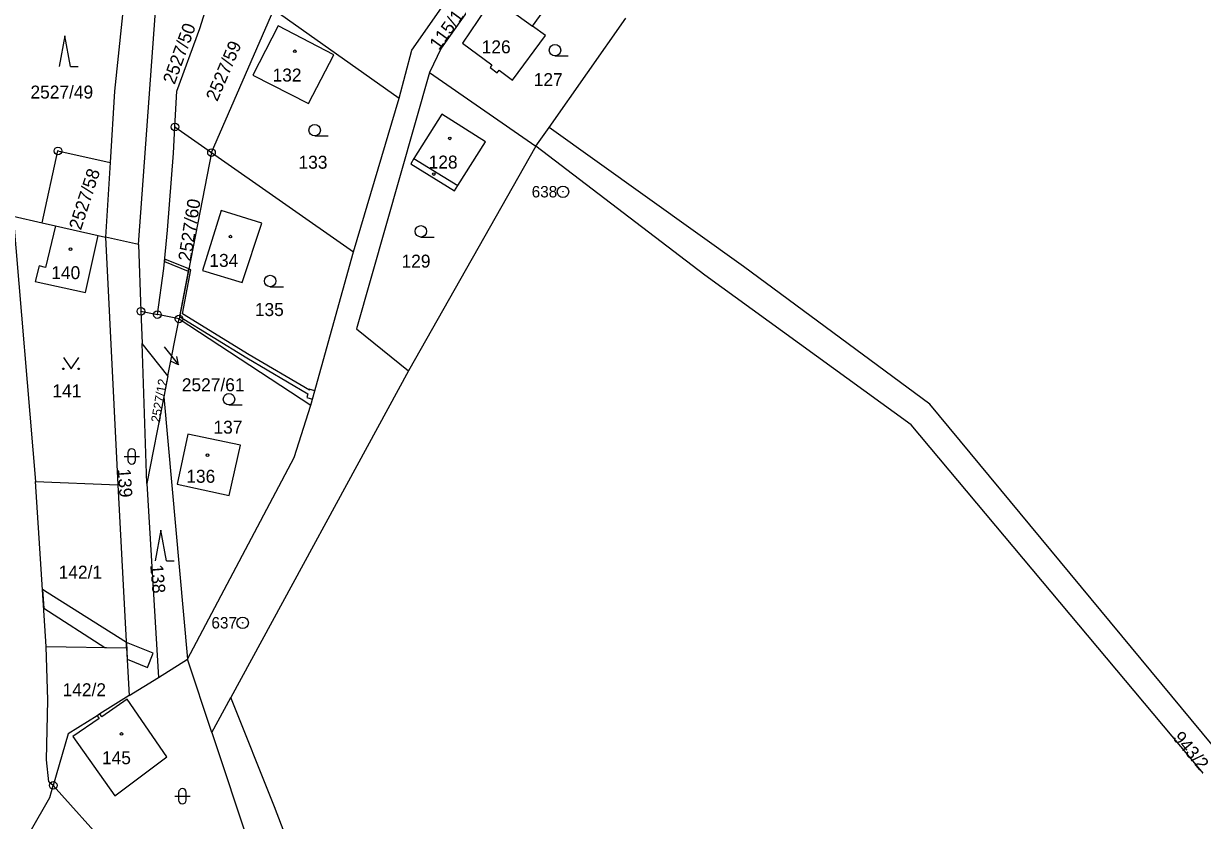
# Model space of a CAD drawing. Extents: x -562167 to -556918, y -1077891 to -1070763.
# Drawn here: x -558717.1 to -558563.6, y -1073031.5 to -1072927 of the extents above; entities that cross this region are included whole.
import ezdxf

# ---------------------------------------------------------------- set-up
doc = ezdxf.new("R2010")
doc.units = 0
for name, color, linetype in [('Hranice parcel', 7, 'Continuous'), ('Parcelní čísla', 7, 'Continuous'), ('Pop  PČ popisy', 7, 'Continuous'), ('Vnitřní kresba', 7, 'Continuous'), ('Věcná břemena k části', 7, 'Continuous'), ('Značky bodu BP', 7, 'Continuous'), ('Značky budov', 7, 'Continuous'), ('Značky kultur', 7, 'Continuous')]:
    doc.layers.add(name, color=color, linetype=linetype)

msp = doc.modelspace()

# ---------------------------------------------------------------- linework, layer by layer
at = {"layer": 'Hranice parcel'}
for p, q in [((-558701.98, -1072956.02), (-558699.1, -1072916.31)), ((-558692.42, -1072943.94), (-558684.24, -1072925.17)), ((-558684.24, -1072925.17), (-558667.85, -1072936.79)), ((-558648.2, -1072940.64), (-558638.13, -1072926.33)), ((-558663.85, -1072933.45), (-558649.94, -1072943.11)), ((-558673.83, -1072956.97), (-558667.85, -1072936.79)), ((-558697.22, -1072940.58), (-558692.42, -1072943.94)), ((-558649.94, -1072943.11), (-558648.2, -1072940.64)), ((-558692.42, -1072943.94), (-558696.67, -1072965.75)), ((-558692.42, -1072943.94), (-558673.83, -1072956.97)), ((-558649.94, -1072943.11), (-558666.61, -1072972.57)), ((-558705.7, -1072945.25), (-558706.29, -1072955.05)), ((-558718.41, -1072952.27), (-558715.49, -1072987.07)), ((-558718.41, -1072952.27), (-558714.62, -1072953.15)), ((-558714.62, -1072953.15), (-558712.86, -1072953.56)), ((-558712.86, -1072953.56), (-558707.25, -1072954.83)), ((-558707.25, -1072954.83), (-558706.29, -1072955.05)), ((-558706.29, -1072955.05), (-558704.68, -1072987.52)), ((-558701.98, -1072956.02), (-558706.29, -1072955.05)), ((-558701.98, -1072956.02), (-558701.67, -1072964.76)), ((-558679.39, -1072977.06), (-558673.83, -1072956.97)), ((-558701.67, -1072964.76), (-558699.51, -1072965.19)), ((-558701.67, -1072964.76), (-558701.52, -1072968.96)), ((-558696.67, -1072965.75), (-558699.51, -1072965.19)), ((-558698.12, -1072973.21), (-558696.67, -1072965.75)), ((-558696.67, -1072965.75), (-558679.39, -1072977.06)), ((-558700.87, -1072987.32), (-558701.52, -1072968.96)), ((-558698.12, -1072973.21), (-558701.52, -1072968.96)), ((-558698.12, -1072973.21), (-558698.66, -1072975.99)), ((-558666.61, -1072972.57), (-558689.88, -1073015.41)), ((-558698.66, -1072975.99), (-558700.87, -1072987.32)), ((-558698.66, -1072975.99), (-558695.57, -1073010.37)), ((-558715.49, -1072987.07), (-558704.68, -1072987.52)), ((-558714.07, -1073008.73), (-558715.49, -1072987.07)), ((-558700.87, -1072987.32), (-558699.38, -1073012.76)), ((-558704.68, -1072987.52), (-558703.54, -1073008.89)), ((-558713.87, -1073015.76), (-558714.07, -1073008.73)), ((-558714.07, -1073008.73), (-558703.54, -1073008.89)), ((-558703.54, -1073008.89), (-558703.2, -1073015.15)), ((-558699.38, -1073012.76), (-558695.57, -1073010.37)), ((-558692.37, -1073019.99), (-558695.57, -1073010.37)), ((-558703.2, -1073015.15), (-558699.38, -1073012.76)), ((-558703.2, -1073015.15), (-558707.03, -1073017.56)), ((-558692.37, -1073019.99), (-558689.88, -1073015.41)), ((-558707.03, -1073017.56), (-558707.39, -1073017.78)), ((-558707.39, -1073017.78), (-558707.14, -1073018.16)), ((-558706.78, -1073017.92), (-558707.03, -1073017.56)), ((-558692.37, -1073019.99), (-558687.05, -1073036.02)), ((-558713.15, -1073026.92), (-558713.74, -1073026.44)), ((-558713.15, -1073026.92), (-558698.1, -1073043.74))]:
    msp.add_line(p, q, dxfattribs=at)
for points in [[(-558702.73, -1072912.92), (-558705.13, -1072935.89), (-558705.7, -1072945.25)], [(-558652.4, -1072916.22), (-558662.34, -1072930.27), (-558663.85, -1072933.45)], [(-558667.85, -1072936.79), (-558666.17, -1072930.51), (-558658.29, -1072919.24)], [(-558648.32, -1072924.55), (-558653.29, -1072920.66), (-558655.5, -1072923.6), (-558659.52, -1072929.61), (-558655.67, -1072932.46), (-558655.92, -1072932.8), (-558655, -1072933.48), (-558654.75, -1072933.14), (-558652.99, -1072934.45), (-558648.65, -1072928.6), (-558650.36, -1072927.35), (-558648.32, -1072924.55)], [(-558697.22, -1072940.58), (-558696.96, -1072935.88), (-558693.96, -1072927.69), (-558692.53, -1072923.19)], [(-558676.41, -1072931.12), (-558683.67, -1072927.34), (-558686.99, -1072933.79), (-558679.71, -1072937.53), (-558676.41, -1072931.12)], [(-558663.85, -1072933.45), (-558673.43, -1072967.05), (-558666.61, -1072972.57)], [(-558662.26, -1072938.92), (-558665.9, -1072944.73), (-558666.32, -1072945.41), (-558660.57, -1072948.95), (-558660.14, -1072948.28), (-558656.54, -1072942.55), (-558662.26, -1072938.92)], [(-558699.51, -1072965.19), (-558698.65, -1072959.15), (-558698.2, -1072954.14), (-558697.41, -1072944.04), (-558697.22, -1072940.58)], [(-558496.99, -1073103.87), (-558502.94, -1073096.71), (-558515.86, -1073079.61), (-558541.04, -1073045.13), (-558560.05, -1073023.14), (-558598.3, -1072976.95), (-558622.72, -1072958.89), (-558648.2, -1072940.64)], [(-558714.62, -1072953.15), (-558712.53, -1072943.72), (-558705.7, -1072945.25)], [(-558501.24, -1073106.42), (-558504.83, -1073102.06), (-558527.47, -1073069.53), (-558543.69, -1073047.48), (-558560.44, -1073027.77), (-558600.75, -1072979.63), (-558627.78, -1072960.02), (-558649.94, -1072943.11)], [(-558691.16, -1072951.54), (-558693.58, -1072959.4), (-558688.39, -1072961), (-558685.83, -1072953.2), (-558691.16, -1072951.54)], [(-558712.86, -1072953.56), (-558714.17, -1072959), (-558715.01, -1072958.8), (-558715.51, -1072960.86), (-558708.94, -1072962.31), (-558707.25, -1072954.83)], [(-558695.57, -1073010.37), (-558681.57, -1072983.94), (-558679.39, -1072977.06)], [(-558690.09, -1072988.89), (-558688.63, -1072982.31), (-558695.51, -1072980.88), (-558696.91, -1072987.44), (-558690.09, -1072988.89)], [(-558713.74, -1073026.44), (-558714.05, -1073023.57), (-558713.87, -1073015.76)], [(-558707.14, -1073018.16), (-558710.58, -1073020.53), (-558705.1, -1073028.3), (-558698.27, -1073023.19), (-558703.45, -1073015.63), (-558706.78, -1073017.92)], [(-558666.41, -1073067.91), (-558673.57, -1073057.52), (-558684.16, -1073029.73), (-558689.88, -1073015.41)], [(-558707.39, -1073017.78), (-558711.21, -1073020.18), (-558713.15, -1073026.92)], [(-558716.16, -1073033.01), (-558713.62, -1073028.53), (-558713.15, -1073026.92)]]:
    msp.add_lwpolyline(points, dxfattribs=at)
at = {"layer": 'Pop  PČ popisy'}
for p, q in [((-558698.61, -1072969.43), (-558696.76, -1072971.79)), ((-558696.76, -1072971.79), (-558697.77, -1072971.31)), ((-558696.76, -1072971.79), (-558696.98, -1072970.7))]:
    msp.add_line(p, q, dxfattribs=at)
at = {"layer": 'Vnitřní kresba'}
for p, q in [((-558655.5, -1072923.6), (-558650.36, -1072927.35)), ((-558665.9, -1072944.73), (-558660.14, -1072948.28))]:
    msp.add_line(p, q, dxfattribs=at)
at = {"layer": 'Věcná břemena k části'}
for points in [[(-558695.46, -1072959.51), (-558695.4, -1072959.21), (-558698.54, -1072957.94), (-558698.57, -1072958.23)], [(-558695.4, -1072959.21), (-558695.46, -1072959.51), (-558696.61, -1072965.46), (-558687.79, -1072970.88), (-558679.78, -1072975.56), (-558679.91, -1072976.08), (-558679.17, -1072976.28), (-558678.88, -1072975.2), (-558679.61, -1072974.97), (-558679.6, -1072975.09), (-558687.5, -1072970.47), (-558696.24, -1072965.1), (-558695.11, -1072959.33)], [(-558714.56, -1073001.24), (-558714.4, -1073003.68), (-558706.38, -1073008.85), (-558703.54, -1073008.89), (-558703.57, -1073008.18), (-558713.93, -1073001.61)], [(-558703.46, -1073010.39), (-558700.82, -1073011.46), (-558700.07, -1073009.6), (-558703.57, -1073008.18)]]:
    msp.add_lwpolyline(points, close=True, dxfattribs=at)
at = {"layer": 'Značky bodu BP'}
for centre, radius in [((-558697.22, -1072940.58), 0.5), ((-558697.22, -1072940.58), 0.0303), ((-558712.53, -1072943.72), 0.5), ((-558712.53, -1072943.72), 0.0303), ((-558692.42, -1072943.94), 0.5), ((-558692.42, -1072943.94), 0.0303), ((-558646.37, -1072949.08), 0.75), ((-558646.37, -1072949.08), 0.03), ((-558701.67, -1072964.76), 0.5), ((-558701.67, -1072964.76), 0.0303), ((-558699.51, -1072965.19), 0.5), ((-558699.51, -1072965.19), 0.0303), ((-558696.67, -1072965.75), 0.5), ((-558696.67, -1072965.75), 0.0303), ((-558688.33, -1073005.6), 0.75), ((-558688.33, -1073005.6), 0.03), ((-558713.15, -1073026.92), 0.5), ((-558713.15, -1073026.92), 0.0303)]:
    msp.add_circle(centre, radius, dxfattribs=at)
at = {"layer": 'Značky budov'}
for centre in [(-558681.51, -1072930.67), (-558661.21, -1072942.08), (-558663.3, -1072946.76), (-558689.95, -1072954.97), (-558710.89, -1072956.6), (-558692.94, -1072983.61), (-558704.22, -1073020.18)]:
    msp.add_circle(centre, 0.175, dxfattribs=at)
at = {"layer": 'Značky kultur'}
for p, q in [((-558711.64, -1072928.64), (-558712.39, -1072932.64)), ((-558710.89, -1072932.64), (-558711.64, -1072928.64)), ((-558647.42, -1072931.27), (-558645.67, -1072931.27)), ((-558710.89, -1072932.64), (-558709.89, -1072932.64)), ((-558678.9, -1072941.76), (-558677.15, -1072941.76)), ((-558664.98, -1072955.02), (-558663.23, -1072955.02)), ((-558684.74, -1072961.54), (-558682.99, -1072961.54)), ((-558690.13, -1072977.04), (-558688.38, -1072977.04)), ((-558703.87, -1072983.78), (-558701.87, -1072983.78)), ((-558703.37, -1072983.28), (-558703.37, -1072984.28)), ((-558702.37, -1072984.28), (-558702.37, -1072983.28)), ((-558699.06, -1072993.47), (-558699.81, -1072997.47)), ((-558698.31, -1072997.47), (-558699.06, -1072993.47)), ((-558698.31, -1072997.47), (-558697.31, -1072997.47)), ((-558697.23, -1073028.34), (-558695.23, -1073028.34)), ((-558696.73, -1073027.84), (-558696.73, -1073028.84)), ((-558695.73, -1073028.84), (-558695.73, -1073027.84))]:
    msp.add_line(p, q, dxfattribs=at)
msp.add_lwpolyline([(-558711.82, -1072970.8), (-558710.82, -1072972.3), (-558709.82, -1072970.8)], dxfattribs=at)
for centre, radius in [((-558647.42, -1072930.52), 0.75), ((-558678.9, -1072941.01), 0.75), ((-558664.98, -1072954.27), 0.75), ((-558684.74, -1072960.79), 0.75), ((-558711.82, -1072972.3), 0.1), ((-558709.82, -1072972.3), 0.1), ((-558690.13, -1072976.29), 0.75)]:
    msp.add_circle(centre, radius, dxfattribs=at)
for centre, start, end in [((-558702.87, -1072983.28), 0, 180), ((-558702.87, -1072984.28), 180, 359.9879), ((-558696.23, -1073027.84), 0, 180), ((-558696.23, -1073028.84), 180, 359.9879)]:
    msp.add_arc(centre, 0.5, start, end, dxfattribs=at)

# ---------------------------------------------------------------- texts
at = {"layer": 'Parcelní čísla'}
for s, height, rotation, p in [('115/1', 1.7, 54, (-558662.62, -1072930.62)), ('2527/50', 1.7, 70, (-558697.25, -1072935.1)), ('2527/59', 1.7, 67, (-558691.66, -1072937.34)), ('2527/58', 1.7, 72, (-558709.53, -1072954.21)), ('2527/60', 1.7, 81, (-558695.13, -1072958.28)), ('2527/12', 1.19, 80, (-558699.19, -1072979.4)), ('139', 1.7, 274, (-558704.72, -1072985.44)), ('138', 1.7, 275, (-558700.46, -1072998.03)), ('943/2', 1.7, 310, (-558566.57, -1073020.72))]:
    msp.add_text(s, height=height, rotation=rotation, dxfattribs=at).set_placement(p)
for s, p in [('126', (-558657.02, -1072930.93)), ('132', (-558684.42, -1072934.63)), ('127', (-558650.2, -1072935.23)), ('2527/49', (-558716.14, -1072936.86)), ('133', (-558681.02, -1072946.06)), ('128', (-558663.97, -1072946.04)), ('134', (-558692.7, -1072958.93)), ('129', (-558667.52, -1072959.03)), ('140', (-558713.41, -1072960.54)), ('135', (-558686.74, -1072965.38)), ('2527/61', (-558696.31, -1072975.24)), ('141', (-558713.26, -1072976.03)), ('137', (-558692.16, -1072980.8)), ('136', (-558695.72, -1072987.24)), ('142/1', (-558712.44, -1072999.81)), ('142/2', (-558711.93, -1073015.23)), ('145', (-558706.77, -1073024.14))]:
    msp.add_text(s, height=1.7, dxfattribs=at).set_placement(p)
at = {"layer": 'Značky bodu BP'}
for s, p in [('638', (-558650.47, -1072949.83)), ('637', (-558692.43, -1073006.35))]:
    msp.add_text(s, height=1.5, dxfattribs=at).set_placement(p)

doc.saveas('drawing.dxf')
